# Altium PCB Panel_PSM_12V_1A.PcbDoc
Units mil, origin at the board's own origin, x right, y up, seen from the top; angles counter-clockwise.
Board outline 1600 x 1200 mil, 2 copper layers (Top Layer, Bottom Layer), stack 62 mil thick; 33 components, 17 nets, 77 pads, 9 vias.
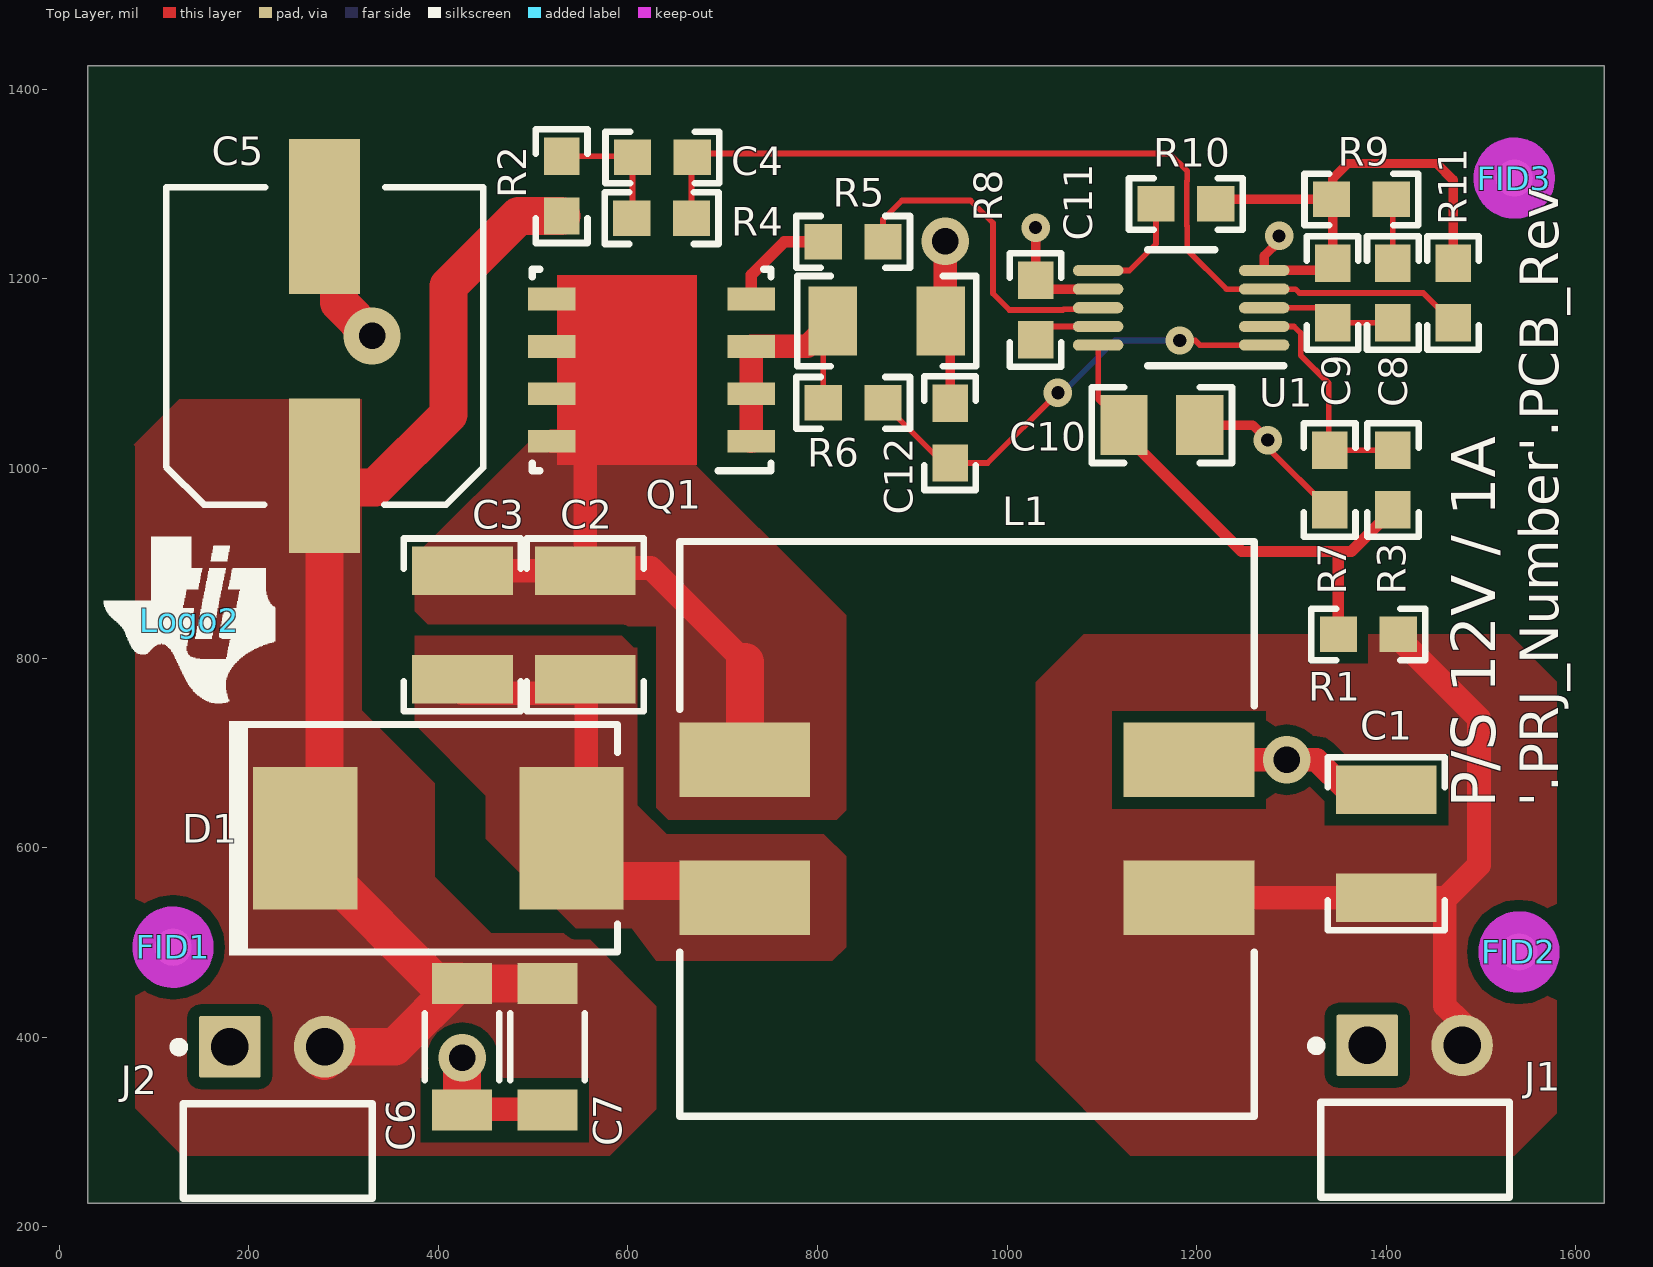
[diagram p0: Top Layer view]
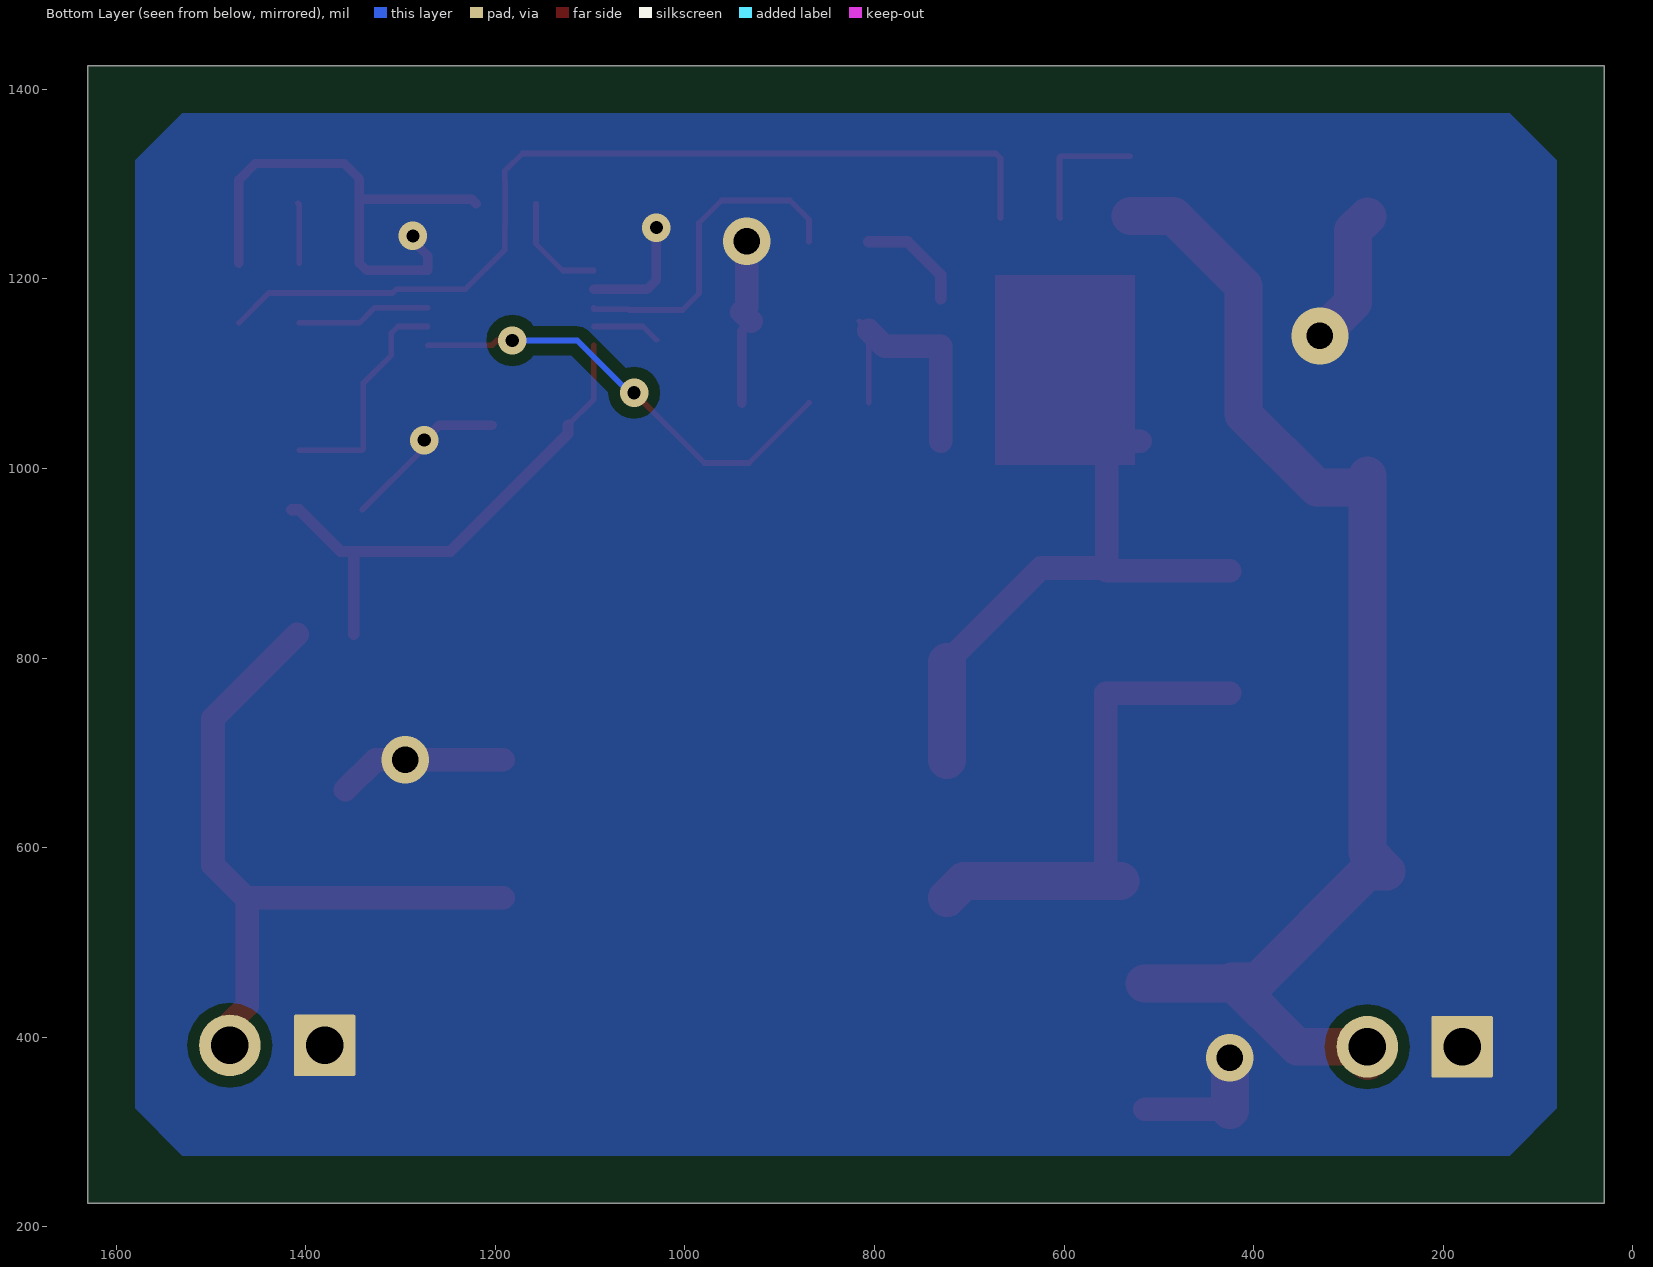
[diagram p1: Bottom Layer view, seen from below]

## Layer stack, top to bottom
Top Solder: solder mask 0.4, Solder Resist, Dk 3.5
Top Layer: signal copper 1.4
Dielectric1: core 59.2, FR-4, Dk 4.8
Bottom Layer: signal copper 1.4
Bottom Solder: solder mask 0.4, Solder Resist, Dk 3.5

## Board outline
30,225 30,1425 1630,1425 1630,225

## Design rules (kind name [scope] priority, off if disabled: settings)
AcuteAngle [All] p1: minimum=4.50000000000000E+0001 checktracksonly=FALSE
AssemblyTestPointUsage [All] p1: valid=2
BoardOutlineClearance BoardOutlineClearance_MountingHoles [OnCopper and InComponentClass('Mounting Holes')] p1: gap=39.37 ignorepadtopadclearanceinfootprint=FALSE
BoardOutlineClearance BoardOutlineClearance_Poly [OnCopper and IsPoly] p2: gap=25 ignorepadtopadclearanceinfootprint=FALSE
BoardOutlineClearance [OnCopper and Not InComponentClass('Logo') and not InComponentClass('FiducialMark') and not InRegion(1000,500,4000,800) and not InPoly] p3: gap=75 ignorepadtopadclearanceinfootprint=FALSE
Clearance Clearance_Keepouts [((IsTrack Or IsArc) And Not InPoly) And IsFree and IsKeepOut vs ((IsTrack Or IsArc) And Not InPoly) And IsFree and IsKeepOut] p1: gap=0 ignorepadtopadclearanceinfootprint=FALSE
Clearance Clearance_Poly [InPolygon] p2: gap=12 ignorepadtopadclearanceinfootprint=TRUE
Clearance Clearance_FiducialMark [IsKeepOut and InComponentClass('FiducialMark') vs IsPad and InComponentClass('FiducialMark')] p3: gap=0 ignorepadtopadclearanceinfootprint=FALSE
Clearance [All] p4: gap=7.87 ignorepadtopadclearanceinfootprint=TRUE
ComponentClearance ComponentClearance_MountingHoles_FiducialMarks [InComponentClass('Mounting Holes') vs InComponentClass('FiducialMark')] p1: gap=50 collisioncheckmode=3 verticalgap=10 showdistances=FALSE
ComponentClearance ComponentClearance_Shunt [InComponentClass('Header') vs InComponentClass('Shunt')] p2: gap=0 collisioncheckmode=3 verticalgap=0 showdistances=FALSE
ComponentClearance ComponentClearance_Logo [InComponentClass('Logo')] p3: gap=20 collisioncheckmode=3 verticalgap=10 showdistances=FALSE
ComponentClearance ComponentClearance_ScrewToNut [(HasFootprint('NY PMS 440 0025 PH')) vs (HasFootprint('Keystone_1902C'))] p4: gap=5 collisioncheckmode=3 verticalgap=10 showdistances=FALSE
ComponentClearance ComponentClearance_MountingHoles [InComponentClass('Mounting Holes')] p5: gap=250 collisioncheckmode=3 verticalgap=100000 showdistances=FALSE
ComponentClearance ComponentClearance_SmallPassives [HasFootprint('0201*') or HasFootprint('0402*') or HasFootprint('0508') or HasFootprint('0603*') or HasFootprint('0612') or HasFootprint('0805*') or HasFootprint('0815*') or HasFootprint('0830*') or HasFootprint('1206*') or HasFootprint('1210*') or HasFootprint('1808*') or HasFootprint('1812*') or HasFootprint('1825*') or HasFootprint('2010*') or HasFootprint('2220*') or HasFootprint('2225*') or HasFootprint('2512*') or HasFootprint('2728*') or HasFootprint('3518*') vs HasFootprint('0201*') or HasFootprint('0402*') or HasFootprint('0508') or HasFootprint('0603*') or HasFootprint('0612') or HasFootprint('0805*') or HasFootprint('0815*') or HasFootprint('0830*') or HasFootprint('1206*') or HasFootprint('1210*') or HasFootprint('1808*') or HasFootprint('1812*') or HasFootprint('1825*') or HasFootprint('2010*') or HasFootprint('2220*') or HasFootprint('2225*') or HasFootprint('2512*') or HasFootprint('2728*') or HasFootprint('3518*')] p6: gap=14.96 collisioncheckmode=3 verticalgap=10 showdistances=FALSE
ComponentClearance ComponentClearance_THtoSMT [IsThruComponent vs IsSMTComponent] p7: gap=40 collisioncheckmode=3 verticalgap=30 showdistances=FALSE
ComponentClearance ComponentClearance_THtoTH [IsThruComponent vs IsThruComponent] p8: gap=30 collisioncheckmode=3 verticalgap=30 showdistances=FALSE
ComponentClearance [All] p9: gap=30 collisioncheckmode=3 verticalgap=10 showdistances=FALSE
DiffPairsRouting [All] p1: maxlimit=100 minlimit=10 mostfreqgap=10 toplayer_minwidth=15 toplayer_maxwidth=15 toplayer_prefwidth=15 bottomlayer_minwidth=15 bottomlayer_maxwidth=15 bottomlayer_prefwidth=15 maxuncoupledlength=1000
FabricationTestPointUsage TestPointUsage [All] p1: valid=2 allowmultiple=FALSE
FabricationTestpoint Testpoint [All] p1: side=3 testpointundercomponent=TRUE minsize=40 maxsize=100 preferedsize=60 minholesize=0 maxholesize=40 preferedholesize=32 testpointgrid=1 allowsidetop=TRUE allowsidebottom=TRUE usegrid=TRUE gridtolerance=0.01
FanoutControl Fanout_LCC [IsLCC] p1: bgadir=Out bgaviamode=Centered fanoutstyle=Auto fanoutdirection=Alternating viagrid=1 // Fanout_LCC (Default Rule)
FanoutControl Fanout_BGA [IsBGA] p2: bgadir=Out bgaviamode=Centered fanoutstyle=Auto fanoutdirection=Alternating viagrid=1 // Fanout_BGA (Default Rule)
FanoutControl Fanout_Default [All] p4: bgadir=Out bgaviamode=Centered fanoutstyle=Auto fanoutdirection=Alternating viagrid=1 // Fanout_Default (Default Rule)
FanoutControl Fanout_Small [(CompPinCount < 5)] p5: bgadir=Out bgaviamode=Centered fanoutstyle=Auto fanoutdirection=OutThenIn viagrid=1 // Fanout_Small (Default Rule)
HoleSize [All] p1: absolutevalues=TRUE maxlimit=251 minlimit=7.87 maxpercent=80.000 minpercent=20.000
MinimumAnnularRing MinimumAnnularRing_ThermalPadVias [IsVia and InAnyComponent] p1: minimumring=5.91
MinimumAnnularRing [All] p2: minimumring=7.87
MinimumSolderMaskSliver MinimumSolderMaskSliver_Logo [InComponentClass('Logo') vs InComponentClass('Logo')] p1: minsoldermaskwidth=0.7
MinimumSolderMaskSliver [All] p2: minsoldermaskwidth=3.94
PlaneConnect [All] p1: planeconnectstyle=Relief reliefexpansion=10 reliefentries=4 reliefconductorwidth=10 reliefairgap=10
PolygonConnect [All] p1: connectstyle=Direct reliefconductorwidth=25 reliefentries=4 polygonreliefangle="90 Angle" airgapwidth=10
RoutingVias ThermalPadVias [IsVia and InAnyComponent] p1: holewidth=7.87 width=19.68 viastyle="Through Hole" minholewidth=7.87 minwidth=19.68 maxholewidth=12.99 maxwidth=23.62
RoutingVias [All] p2: holewidth=16 width=34 viastyle="Through Hole" minholewidth=7.87 minwidth=26 maxholewidth=40 maxwidth=65
SilkToBoardRegionClearance [Not ((IsComment or IsDesignator) And (Hide <> 'False')) and not InRegion(1000,500,4000,800)] p1:
SilkToSilkClearance SilkToSilkClearance_Pb-FreeLogo [(HasFootprint('Pb-Free_Overlay_Medium') OR HasFootprint('Pb-Free_Overlay_Small')) vs (HasFootprint('Pb-Free_Overlay_Medium') OR HasFootprint('Pb-Free_Overlay_Small'))] p1: silktosilkclearance=0
SilkToSilkClearance [All] p2: silktosilkclearance=3.94
SilkToSolderMaskClearance SilkToComponentPadClearance [(IsPad or IsFill or IsRegion) and InAnycomponent] p1: minsilkscreentomaskgap=5 clearancetoexposedcopper=TRUE
SilkToSolderMaskClearance "Silk to Solder Mask Opening" [All] p2: minsilkscreentomaskgap=3.94 clearancetoexposedcopper=FALSE
SolderMaskExpansion [All] p1: expansion=1.97
UnRoutedNet [All] p1: checkbadconnections=TRUE
Width [All] p1: maxlimit=100 minlimit=6 preferedwidth=10 checkconnectedcopper=TRUE
14 further rules are at their usual default settings.

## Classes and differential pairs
component class Logo: Logo2
component class Hardware: FID1 FID2 FID3 Logo2
component class FiducialMark: FID1 FID2 FID3

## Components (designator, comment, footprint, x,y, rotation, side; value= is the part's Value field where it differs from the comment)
C1 "C3225X7S2A335M200AB" 1210 1400,604.12 r90 top value=3.3uF
C2 "C3225X7S2A335M200AB" 1210 554.85,834.98 r270 top value=3.3uF
C3 "C3225X7S2A335M200AB" 1210 425.27,834.98 r270 top value=3.3uF
C4 "C0603C474K8PACTU" 0603 636.27,1328.22 r0 top value=0.47uF
C5 "25SVPF180M" SVPF_E12 280,1129.26 r90 top value=180uF
C6 "EMK316BB7226ML-T" 1206_190 424.8,390 r270 top value=22uF
C7 "EMK316BB7226ML-T" 1206_190 515,390 r270 top value=22uF
C8 "C1608X7R1C105K080AC" 0603 1406.97,1185.17 r90 top value=1uF
C9 "C0603C474K8PACTU" 0603 1343.35,1185.17 r90 top value=0.47uF
C10 "C2012X7R2A104K125AA" 0805_HV 1163.28,1045.89 r0 top value=0.1uF
C11 "C1608X7R1C105K080AC" 0603 1030,1167.26 r90 top value=1uF
C12 "C0603X102K5RACTU" 0603 939.84,1037.39 r90 top value=1000pF
D1 "DIODE_SCHOTTKY" SMC 400,610 r0 top value=100V
FID1 "Fiducial" Fiducial10-20 120,495 r0 top
FID2 "Fiducial" Fiducial10-20 1540,490 r0 top
FID3 "Fiducial" Fiducial10-20 1535,1306.44 r0 top
J1 "TSW-102-08-G-S-RA" TSW-102-08-G-S-RA 1430,391.42 r0 top
J2 "TSW-102-08-G-S-RA" TSW-102-08-G-S-RA 230,390 r0 top
L1 "INDUCTOR_COUPLED_13_24" IND_MSD1583 957.61,619.87 r180 top value=47uH
Logo2 "Texas Instruments" TI_Symbol_Overlay_Small 137.29,840 r0 top
Q1 "FDMS86101" TRANS_Fairchild_PQFN08A 624.88,1103.89 r180 top value=100V
R1 "Resistor" 0603 1381,825 r0 top value=10
R2 "Resistor" 0603 530,1297.95 r270 top value=49.9
R3 "Resistor" 0603 1406.97,987.96 r270 top value=100k
R4 "Resistor" 0603 635.45,1264.16 r180 top value=49.9k
R5 "Resistor" 0603 837.48,1239.25 r180 top value=0
R6 "Resistor" 0603 837.48,1069.26 r0 top value=221
R7 "Resistor" 0603 1340.34,987.96 r90 top value=33.2k
R8 "Resistor" 1206 872.91,1155.44 r180 top value=0.01
R9 "Resistor" 0603 1373.67,1283.91 r0 top value=1.50k
R10 "Resistor" 0603 1188.5,1279.24 r180 top value=105k
R11 "Resistor" 0603 1470.47,1185.17 r270 top value=5.90k
U1 "LM3481QMM/NOPB" DGS0010A_N 1183.6,1169.59 r180 top

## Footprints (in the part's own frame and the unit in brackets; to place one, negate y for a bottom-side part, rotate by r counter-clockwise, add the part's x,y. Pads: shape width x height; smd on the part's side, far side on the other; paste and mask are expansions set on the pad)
0603 [mm] "0603 from SM-752 data"
  rect 1x0.95 smd: 1(-0.8,0) 2(0.8,0)
  silkscreen extent -1.52,-0.69 1.52,0.69, body extent -0.87,-0.47 0.87,0.47, height 1
0805_HV [mil] "0805 with 30mil clearance between pads"
  rect 50x63 smd: 1(-40,0) 2(40,0)
  silkscreen extent -74,-40 74,40, body extent -43,-29 43,29, height 57
1206 [mm] "1206 from SM-752 data"
  rect 1.3x1.85 smd: 1(-1.45,0) 2(1.45,0)
  silkscreen extent -2.4,-1.21 2.4,1.21, body extent -1.7,-0.9 1.7,0.9, height 1.35
1206_190 [mm] "1206_190"
  rect 1.1x1.6 smd: 1(-1.7,0) 2(1.7,0)
  silkscreen extent -0.9,-1 0.9,1, body extent -1.75,-0.95 1.75,0.95, height 1.9
1210 [mm] "1210 from SM-752 data"
  rect 1.3x2.7 smd: 1(-1.45,0) 2(1.45,0)
  silkscreen extent -2.32,-1.57 2.32,1.57, body extent -1.7,-1.35 1.7,1.35, height 1.35
DGS0010A_N [mm] "TSSOP, 10-Leads, Body 3x3mm, Pitch 0.5mm, IPC Medium Density"
  oval 1.35x0.3 smd: 1(-2.225,1) 2(-2.225,0.5) 3(-2.225,0) 4(-2.225,-0.5) 5(-2.225,-1) 6(2.225,-1) 7(2.225,-0.5) 8(2.225,0) 9(2.225,0.5) 10(2.225,1)
  silkscreen extent -2.75,-1.55 0.9,1.55, body extent -2.45,-1.5 2.45,1.5, height 0.96
Fiducial10-20 [mm]
  round 1 smd mask+0.5: 1(0,0)
  Top Layer keep-out circle w1.178: c0,0 r0.5
IND_MSD1583 [mm] "COILCRAFT"
  rect 3.5x2 smd: 1(-5.95,1.85) 2(-5.95,-1.85) 3(5.95,-1.85) 4(5.95,1.85)
  silkscreen extent -7.7,-7.7 7.7,7.7, body extent -7.55,-7.55 7.55,7.55, height 8.6
SMC [mil] "Molded Diode, 2-Leads, Body 6.9x5.8mm, IPC Medium Density, based on OnSemi component dimensions and land patterns"
  rect 110x150 smd: 1(-140.49,0) 2(140.49,0)
  silkscreen extent -221,-123 189,124, body extent -156,-116 156,116, height 91
SVPF_E12 [mm] "OS-CON  8x10"
  rect 4.15x1.9 smd: 1(-3.475,0) 2(3.475,0)
  silkscreen extent -4.25,-4.25 4.25,4.25, body extent -4.25,-4.25 4.25,4.25, height 12
TI_Symbol_Overlay_Small [mil]
  silkscreen extent -90,-88 91,88
TRANS_Fairchild_PQFN08A [mm] "Fairchild PQFN08A recommended land pattern"
  rect 1.27x0.61 smd: 1(-2.67,1.905) 2(-2.67,0.635) 3(-2.67,-0.635) 4(-2.67,-1.905) 5(2.67,-1.905) 6(2.67,-0.635) 7(2.67,0.635) 8(2.67,1.905)
  Top Layer region: -1.215,-2.55 2.535,-2.55 2.535,2.55 -1.215,2.55
  silkscreen extent -3.2,-2.7 3.2,2.7, body extent -3.05,-2.55 3.05,2.55, height 1.11
TSW-102-08-G-S-RA [mm] "Samtec Right Angle Header"
  rrect6% 1.65x1.65 hole 1: 1(-1.27,0)
  round 1.65 hole 1: 2(1.27,0)
  silkscreen extent -2.76,-4.06 2.54,0.11, body extent -2.54,-9.91 2.54,0.32, height 3.05

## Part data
C1 C2 C3: library part CMP-0009133-1, "CAP, CERM, 3.3 uF, 100 V, +/- 20%, X7S, 1210", Cap_Case=1210, Manufacturer=TDK, Supplier Part Number 1=445-5210-1-ND, TempCo=X7S, Tolerance_%=20%, Value1=Unknown, Value2=100V, ValueDisplayed=3.3uF
C4 C9: library part CMP-0006945-5, "CAP, CERM, 0.47 uF, 10 V, +/- 10%, X5R, 0603", Cap_Case=0603, Manufacturer=Kemet, Supplier Part Number 1=399-3114-1-ND, TempCo=X5R, Tolerance_%=10%, Value1=Unknown, Value2=10V, ValueDisplayed=0.47uF
C5: library part CMP-0012118-3, "CAP, Aluminum Polymer, 180 uF, 25 V, +/- 20%, 0.016 ohm, 2-Pin SMD, Body 8.3 x 8.3 mm, Height 12 mm SMD", Cap_Case=8.0x11.9, Manufacturer=Panasonic, Supplier Part Number 1=P16510CT-ND, Tolerance_%=20%, Value1="0.016 ohm", Value2=25V, ValueDisplayed=180uF
C6 C7: library part CMP-0008805-2, "CAP, CERM, 22 uF, 16 V, +/- 20%, X7R, 1206_190", Cap_Case=1206, Manufacturer="Taiyo Yuden", Supplier Part Number 1=587-4319-1-ND, TempCo=X7R, Tolerance_%=20%, Value1=Unknown, Value2=16V, ValueDisplayed=22uF
C8 C11: library part CMP-0007037-4, "CAP, CERM, 1 uF, 16 V, +/- 10%, X7R, 0603", Cap_Case=0603, Manufacturer=TDK, Supplier Part Number 1=445-1604-1-ND, TempCo=X7R, Tolerance_%=10%, Value1="0.0057 ohm", Value2=16V, ValueDisplayed=1uF
C10: library part CMP-0007886-2, "CAP, CERM, 0.1 uF, 100 V, +/- 10%, X7R, 0805", Cap_Case=0805, Manufacturer=TDK, Supplier Part Number 1=445-1418-1-ND, TempCo=X7R, Tolerance_%=10%, Value1="0.020726 ohm", Value2=100V, ValueDisplayed=0.1uF
C12: library part CMP-0006976-5, "CAP, CERM, 1000 pF, 50 V, +/- 10%, X7R, 0603", Cap_Case=0603, Manufacturer=Kemet, Supplier Part Number 1=399-5348-1-ND, TempCo=X7R, Tolerance_%=10%, Value1=Unknown, Value2=50V, ValueDisplayed=1000pF
D1: library part CMP-0028531-2, "Diode, Schottky, 100 V, 3 A, SMC", Manufacturer="ON Semiconductor", PartNumber=MBRS3100T3G, Value1=3A, Value2=0.62V
FID1 FID2 FID3: library part CMP-0077181-1, "Fiducial mark.  There is nothing to buy or mount.", Manufacturer=N/A
J1 J2: library part CMP-0055976-1, "Header, 100mil, 2x1, Gold, R/A, TH", Color=Black, Current_A=6.3A, Manufacturer=Samtec, Supplier Part Number 1=SAM1039-02-ND, Voltage_V=550V
L1: library part CMP-0076818-2, "Coupled inductor, 47 µH, 6.7 A, 0.1 ohm, SMD", Manufacturer=Coilcraft, PartNumber=MSD1583-473MEB, Supplier Part Number 1=994-MSD1583-473MEB, ValueDisplayed=47µH
Logo2: library part CMP-0074838-1, "Texas Instrument Corporate Signature"
Q1: library part CMP-0000984-1, "MOSFET, N-CH, 100 V, 60 A, PQFN08A", Alternate Manufacturer=None, Manufacturer="Fairchild Semiconductor", Supplier Part Number 1=FDMS86101CT-ND, Value2="39 nC"
R1: library part CMP-0025703-4, "RES, 10, 5%, 0.1 W, AEC-Q200 Grade 0, 0603", Manufacturer=Vishay-Dale, PartNumber=CRCW060310R0JNEA, Power_W=100mW, Supplier Part Number 1=541-10GCT-ND, TempCo="200 ppm/C", Tolerance_%=5%, Value2=0.1W, Value_Code=10R0, ValueDisplayed=10
R2: library part CMP-0022448-4, "RES, 49.9, 1%, 0.1 W, AEC-Q200 Grade 0, 0603", Manufacturer=Vishay-Dale, PartNumber=CRCW060349R9FKEA, Power_W=100mW, Supplier Part Number 1=541-49.9HCT-ND, TempCo="100 ppm/C", Tolerance_%=1%, Value2=0.1W, Value_Code=49R9, ValueDisplayed=49.9
R3: library part CMP-0021990-4, "RES, 100 k, 1%, 0.1 W, AEC-Q200 Grade 0, 0603", Manufacturer=Vishay-Dale, PartNumber=CRCW0603100KFKEA, Power_W=100mW, Supplier Part Number 1=541-100KHCT-ND, TempCo="100 ppm/C", Tolerance_%=1%, Value2=0.1W, Value_Code=100k
R4: library part CMP-0022447-4, "RES, 49.9 k, 1%, 0.1 W, AEC-Q200 Grade 0, 0603", Manufacturer=Vishay-Dale, PartNumber=CRCW060349K9FKEA, Power_W=100mW, Supplier Part Number 1=541-49.9KHCT-ND, TempCo="100 ppm/C", Tolerance_%=1%, Value2=0.1W, Value_Code=49k9, ValueDisplayed=49.9k
R5: library part CMP-0025697-4, "RES, 0, 5%, 0.1 W, AEC-Q200 Grade 0, 0603", Manufacturer=Vishay-Dale, PartNumber=CRCW06030000Z0EA, Power_W=100mW, Supplier Part Number 1=541-0.0GCT-ND, TempCo="200 ppm/C", Tolerance_%=5%, Value2=0.1W, Value_Code=0000, ValueDisplayed=0
R6: library part CMP-0022217-5, "RES, 221, 1%, 0.1 W, AEC-Q200 Grade 0, 0603", Manufacturer=Vishay-Dale, PartNumber=CRCW0603221RFKEA, Power_W=100mW, Supplier Part Number 1=541-221HCT-ND, TempCo="100 ppm/C", Tolerance_%=1%, Value2=0.1W, Value_Code=221R, ValueDisplayed=221
R7: library part CMP-0022339-4, "RES, 33.2 k, 1%, 0.1 W, AEC-Q200 Grade 0, 0603", Manufacturer=Vishay-Dale, PartNumber=CRCW060333K2FKEA, Power_W=100mW, Supplier Part Number 1=541-33.2KHCT-ND, TempCo="100 ppm/C", Tolerance_%=1%, Value2=0.1W, Value_Code=33k2, ValueDisplayed=33.2k
R8: library part CMP-0017256-2, "RES, 0.01, 1%, 0.5 W, 1206", Manufacturer="Stackpole Electronics Inc", PartNumber=CSR1206FK10L0, Power_W=500mW, Supplier Part Number 1=CSR1206FK10L0CT-ND, TempCo="100 ppm/C", Tolerance_%=1%, Value2=0.5W, Value_Code=R010, ValueDisplayed=0.01
R9: library part CMP-0022126-4, "RES, 1.50 k, 1%, 0.1 W, AEC-Q200 Grade 0, 0603", Manufacturer=Vishay-Dale, PartNumber=CRCW06031K50FKEA, Power_W=100mW, Supplier Part Number 1=541-1.50KHCT-ND, TempCo="100 ppm/C", Tolerance_%=1%, Value2=0.1W, Value_Code=1k50, ValueDisplayed=1.50k
R10: library part CMP-0021994-4, "RES, 105 k, 1%, 0.1 W, AEC-Q200 Grade 0, 0603", Manufacturer=Vishay-Dale, PartNumber=CRCW0603105KFKEA, Power_W=100mW, Supplier Part Number 1=541-105KHCT-ND, TempCo="100 ppm/C", Tolerance_%=1%, Value2=0.1W, Value_Code=105k
R11: library part CMP-0022515-4, "RES, 5.90 k, 1%, 0.1 W, AEC-Q200 Grade 0, 0603", Manufacturer=Vishay-Dale, PartNumber=CRCW06035K90FKEA, Power_W=100mW, Supplier Part Number 1=541-5.90KHCT-ND, TempCo="100 ppm/C", Tolerance_%=1%, Value2=0.1W, Value_Code=5k90, ValueDisplayed=5.90k
U1: library part CMP-0071928-2, "High Efficiency Low-Side N-Channel Controller for Switching Regulators, AEC-Q100 Grade 1, 10-pin Mini SOIC, 1000 Reel", Alternate Manufacturer="Texas Instruments", Alternate PartNumber=LM3481QMMX/NOPB

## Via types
v1: diameter 30, hole 14, Top Layer to Bottom Layer, 5 vias
v2: diameter 50, hole 28, Top Layer to Bottom Layer, 3 vias
v3: diameter 60, hole 28, Top Layer to Bottom Layer, 1 vias

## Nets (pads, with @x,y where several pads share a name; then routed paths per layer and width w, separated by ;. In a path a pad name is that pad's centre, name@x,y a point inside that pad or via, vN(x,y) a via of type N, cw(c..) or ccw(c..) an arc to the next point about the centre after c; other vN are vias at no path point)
GND: C1.2 C5.2 C6.2 C7.2 C9.2 C10.2 C11.2 C12.2 J1.1 J2.1 L1.2 R7.1 R8.1 R9.1 R10.1 R11.1 U1.5 U1.7 | length 1519.9
  Top Layer w6: v1(1275,1030) 1275,1021.81 R7.1
  Top Layer w10: R8.1 939.84,1145.6 C12.2 ; v1@1030,1255 v1(1030,1254.24) C11.2 1039.48,1189.28 U1.7 ; C10.2 1259.11,1045.89 v1(1275,1030) ; R10.1 1224.67,1283.91 R9.1 R9.1@1343.35,1282.73 ; v1(1286.87,1245.46) 1286.87,1240.15 1271.2,1224.48 U1.5 1335.64,1208.96 C9.2 R9.1@1343.35,1282.73 ; R11.1 1470.47,1304.6 1453.25,1321.83 1359.38,1321.83 1343.35,1305.8 R9.1@1343.35,1282.73
  Top Layer w25: C6.2@424.8,324.17 C7.2@514.8,324.17 ; R8.1 939.84,1165.29 934.84,1170.29 v2(934.84,1240) ; L1.2 v2(1295,692.7) 1326.44,692.7 C1.2@1357.93,661.21
  Top Layer w40: C5.2 295,1251.07 295,1175 v3(330,1140) ; C6.2 424.8,324.17 424.8,377.92 v2(425.27,378.39)
NetC1_1: C1.1 J1.2 L1.1 R1.2 | length 782.6
  Top Layer w25: L1.1 C1.1 1459.32,547.03 ; R1.2@1409.05,825 1497.74,736.31 1497.74,581.78 1462.99,547.03 1459.32,547.03 ; J1.2@1479.49,373.05 1479.49,415.51 1461.72,433.28 1461.72,544.63 1459.32,547.03
NetC2_1: C2.1 C3.1 L1.3 Q1.5 Q1.6 Q1.7 Q1.8 | length 614.1
  Top Layer w25: C3.1 C2.1 C2.1@554.85,895 ; Q1.8 554.85,1028.89 C2.1@554.85,895 ; 723.35,795.73 624.09,895 C2.1@554.85,895
  Top Layer w40: L1.3 723.35,795.73
NetC2_2: C2.2 C3.2 D1.2 L1.4 | length 524.1
  Top Layer w25: C3.2@425.27,762.89 C2.2@554.85,762.89 ; D1.2@540.49,565 555.85,580.36 C2.2@555.85,762.89
  Top Layer w40: D1.2@540.49,565 705.39,565 L1.4
NetC4_1: C4.1 R2.1 R4.2 | length 139.7
  Top Layer w6: R2.1 603.55,1329.44 C4.1 604.77,1264.97 R4.2
NetC4_2: C4.2 R4.1 R11.2 U1.4 | length 992.1
  Top Layer w6: R4.1 666.95,1327.4 C4.2 671.94,1332.39 1171.45,1332.39 1190,1313.85 1190,1303.57 1189.44,1303.01 1189.44,1256.04 1190,1255.48 1190,1230.61 1231.34,1189.28 U1.4 1304.29,1189.28 1308.4,1185.17 1438.98,1185.17 R11.2
NetC8_1: C8.1 C9.1 U1.3 | length 142.4
  Top Layer w6: U1.3 1327.43,1169.59 C9.1 C8.1
NetC8_2: C8.2 R9.2 | length 63.7
  Top Layer w6: C8.2 1406.97,1278.72 R9.2@1408.11,1279.87
NetC10_1: C10.1 R1.1 R3.2 U1.10 | length 553.6
  Top Layer w6: U1.10 1096,1073.17 C10.1
  Top Layer w12: C10.1 1123.28,1036.72 1247.5,912.5 1350,912.5 ; R1.1 1349.51,912.01 1350,912.5 ; R3.2@1414.74,956.47 R3.2 1363,912.5 1350,912.5
NetC11_1: C11.1 U1.9 | length 71.9
  Top Layer w6: C11.1 1044.15,1149.91 U1.9
NetC12_1: C12.1 R6.2 U1.1 | length 484
  Top Layer w6: R6.2 932.35,1005.89 C12.1 979.44,1005.89 v1(1053.55,1080) ; v1(1182.01,1135.09) 1198.42,1135.09 1203.28,1130.22 U1.1
  Bottom Layer w6: v1(1053.55,1080) 1058.4,1080 1113.49,1135.09 v1(1182.01,1135.09)
NetQ1_1: Q1.1 Q1.2 Q1.3 R6.1 R8.2 | length 273.2
  Top Layer w6: R6.1 805.98,1145.6 R8.2
  Top Layer w25: Q1.1 Q1.2 Q1.3 789.27,1128.89 R8.2@805.98,1145.6
NetQ1_4: Q1.4 R5.2 | length 115.9
  Top Layer w12: Q1.4 730,1204.28 764.97,1239.25 R5.2
NetR3_1: R3.1 R7.2 U1.2 | length 244.2
  Top Layer w6: U1.2 1302.71,1149.91 1309.66,1142.96 1309.66,1119.57 1339.23,1090 1339.23,1020.57 R7.2 R3.1
NetR5_1: R5.1 U1.8 | length 352
  Top Layer w6: R5.1 868.98,1262.7 889.01,1282.73 961.36,1282.73 985,1259.1 985,1184.64 1002.39,1167.26 1058.54,1167.26 1059.48,1168.19 1096,1168.19 U1.8
NetR10_2: R10.2 U1.6 | length 114.9
  Top Layer w6: U1.6 1128.96,1208.96 1157.01,1237.01 R10.2
Vout: C5.1 C6.1 C7.1 D1.1 J2.2 R2.2 | length 1364.8
  Top Layer w40: J2.2@280,375 J2.2 353.94,390 C6.1@422.83,458.9 ; C5.1 C5.1@280,980 ; C7.1 C6.1 C6.1@422.83,458.9 ; R2.2 484.38,1266.45 410.51,1192.58 410.51,1057.18 333.34,980 C5.1@280,980 ; C5.1@280,980 280,595.31 259.51,574.81 280.19,574.81 396.1,458.9 C6.1@422.83,458.9
pads on no net: FID1.1 FID2.1 FID3.1

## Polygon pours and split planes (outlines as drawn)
GND on Bottom Layer "BOTTOM_LAYER_GND_P000" (solid, remove dead copper, pour order 0): 80,325 130,275 1530,275 1580,325 1580,1325 1530,1375 130,1375 80,1325
Vout on Top Layer "TOP_LAYER_VOUT_P008" (solid, remove dead copper, pour order 8): 318.85,1072.95 126.73,1072.95 78.78,1025 80,1023.78 80,325 130,275 580.83,275 630,324.17 630,432.98 552.98,510 455.59,510 396.1,569.49 396.1,667.74 318.85,744.99
NetC2_1 on Top Layer "TOP_LAYER_NETC2_1_P006" (solid, remove dead copper, pour order 6): 375,901.91 375,849.46 391.18,833.28 391.54,833.65 630,833.65 630,629.68 820,629.68 830,639.68 830,845 645,1030 497.5,1030 380,912.5
NetC2_2 on Top Layer "TOP_LAYER_NETC2_2_P004" (solid, remove dead copper, pour order 4): 375,823.47 375,730 450,655 450,609.68 544.68,515 603.79,515 630,480.68 815.68,480.68 830,495 830,590.75 806.69,614.06 640.94,614.06 610,645 610,810.75 606.11,810.75 593.39,823.47
NetC1_1 on Top Layer "TOP_LAYER_NETC1_1_P002" (solid, remove dead copper, pour order 2): 1535,275 1580,320 1580,775 1530,825 1080.6,825 1029.96,774.36 1029.96,375.03 1130,275

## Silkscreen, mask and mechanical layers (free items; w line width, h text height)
Top Overlay:
  text "'.PRJ_Number'.PCB_Rev" at 1595,643.33 h70 r90
  text "P/S 12V / 1A" at 1530,642.3 h80 r90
